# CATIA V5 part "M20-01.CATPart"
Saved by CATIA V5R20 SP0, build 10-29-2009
Part number: M20-01
Revision: ANY
Definition: UNKNOWN
Nomenclature: M20-01
Source: Unknown
Bounding box of the stored display mesh (mm): x -10 to 10, y -10 to 10, z 0 to 290
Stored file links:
  C:\Users\Utente\Desktop\IO LAVORO\3D X SITO CF\X 3D SITO CF 27-09-2020\740T\740T-20\M20-01.CATPart
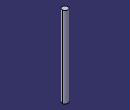
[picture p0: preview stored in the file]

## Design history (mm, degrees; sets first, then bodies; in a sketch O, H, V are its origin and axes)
Body1 "NONE" (main body)
  Solid1: solid without history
